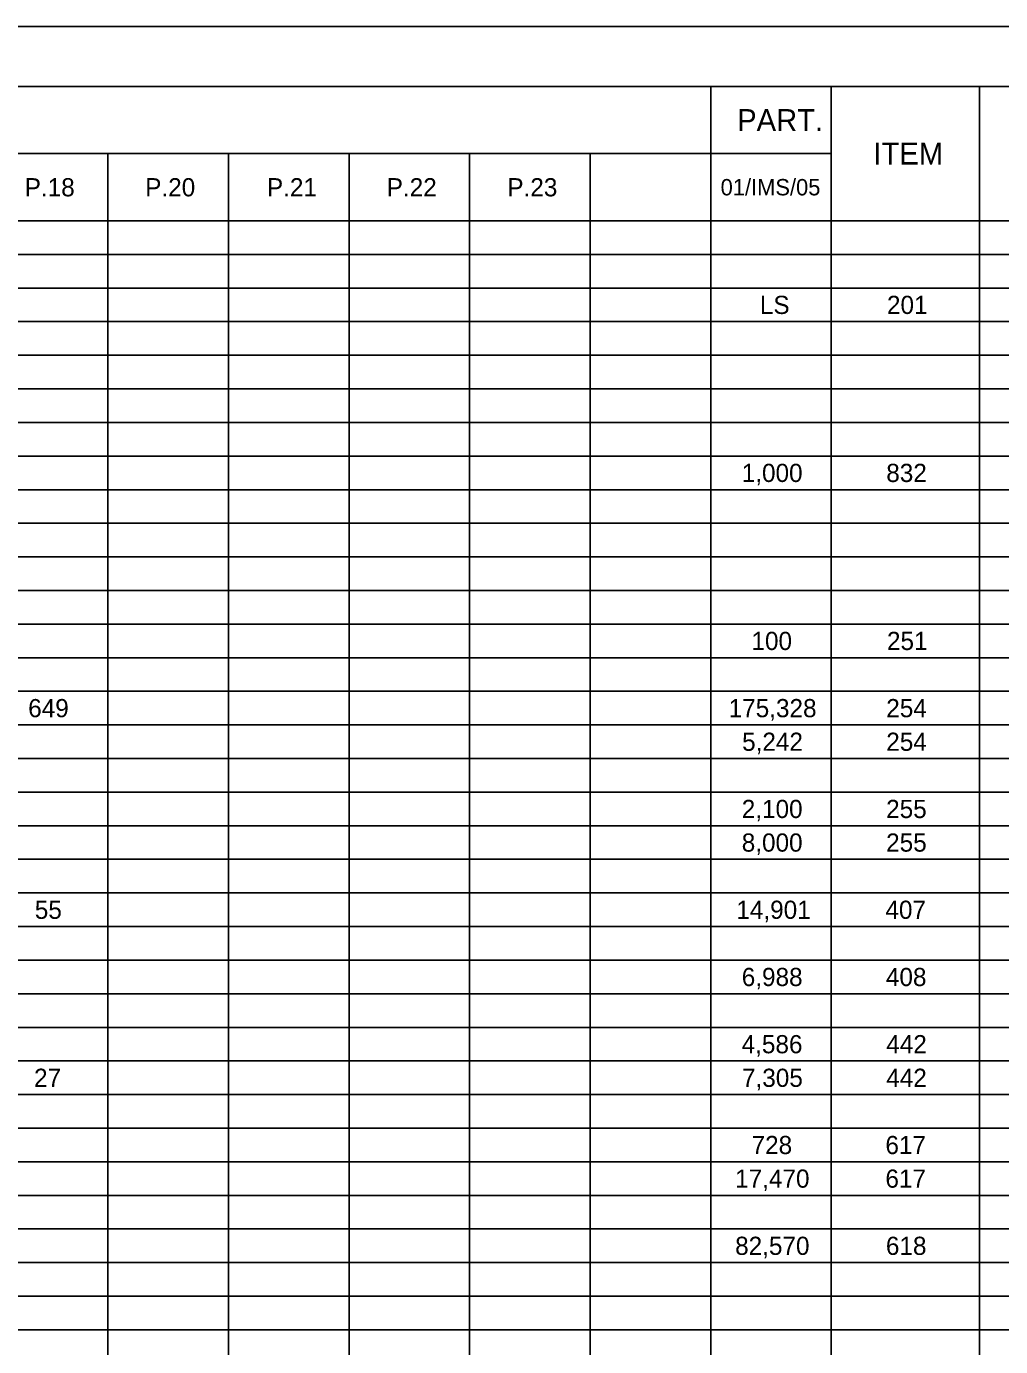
# Model space of a CAD drawing. Extents: x 0 to 806, y -250 to 22.
# Drawn here: x 8.86 to 16.97, y 11 to 22 of the extents above; entities that cross this region are included whole.
import ezdxf

# ---------------------------------------------------------------- set-up
doc = ezdxf.new("R2010")
doc.units = 0
for name, color, linetype in [('SH_Border', 7, 'Continuous'), ('SH_Cut_Line', 7, 'Continuous'), ('SH_Text', 7, 'Continuous')]:
    doc.layers.add(name, color=color, linetype=linetype)

msp = doc.modelspace()

# ---------------------------------------------------------------- linework, layer by layer
at = {"layer": 'SH_Border'}
msp.add_lwpolyline([(1.5, 21.5), (33.5, 21.5), (33.5, 0.5), (1.5, 0.5)], close=True, dxfattribs=at)
at = {"layer": 'SH_Cut_Line'}
msp.add_lwpolyline([(0, 0), (34, 0), (34, 22), (0, 22)], close=True, dxfattribs=at)
at = {"layer": 'SH_Text'}
for p, q in [((1.5, 21.5), (32, 21.5)), ((14.56, 21.5), (14.56, 0.5)), ((15.564, 21.5), (15.564, 0.5)), ((16.799, 21.5), (16.799, 0.5)), ((1.5, 20.94), (15.564, 20.94)), ((9.537, 20.94), (9.537, 0.5)), ((10.541, 20.94), (10.541, 0.5)), ((11.546, 20.94), (11.546, 0.5)), ((12.55, 20.94), (12.55, 0.5)), ((13.555, 20.94), (13.555, 0.5)), ((1.5, 20.38), (32, 20.38)), ((1.5, 20.1), (32, 20.1)), ((1.5, 19.82), (32, 19.82)), ((1.5, 19.54), (32, 19.54)), ((1.5, 19.26), (32, 19.26)), ((1.5, 18.98), (32, 18.98)), ((1.5, 18.7), (32, 18.7)), ((1.5, 18.42), (32, 18.42)), ((1.5, 18.14), (32, 18.14)), ((1.5, 17.86), (32, 17.86)), ((1.5, 17.58), (32, 17.58)), ((1.5, 17.3), (32, 17.3)), ((1.5, 17.02), (32, 17.02)), ((1.5, 16.74), (32, 16.74)), ((1.5, 16.46), (32, 16.46)), ((1.5, 16.18), (32, 16.18)), ((1.5, 15.9), (32, 15.9)), ((1.5, 15.62), (32, 15.62)), ((1.5, 15.34), (32, 15.34)), ((1.5, 15.06), (32, 15.06)), ((1.5, 14.78), (32, 14.78)), ((1.5, 14.5), (32, 14.5)), ((1.5, 14.22), (32, 14.22)), ((1.5, 13.94), (32, 13.94)), ((1.5, 13.66), (32, 13.66)), ((1.5, 13.38), (32, 13.38)), ((1.5, 13.1), (32, 13.1)), ((1.5, 12.82), (32, 12.82)), ((1.5, 12.54), (32, 12.54)), ((1.5, 12.26), (32, 12.26)), ((1.5, 11.98), (32, 11.98)), ((1.5, 11.7), (32, 11.7)), ((1.5, 11.42), (32, 11.42)), ((1.5, 11.14), (32, 11.14))]:
    msp.add_line(p, q, dxfattribs=at)

# ---------------------------------------------------------------- texts
for s, height, p in [('PART.', 0.1818, (14.78, 21.129)), ('ITEM', 0.1818, (15.915, 20.849)), ('P.18', 0.1515, (8.844, 20.584)), ('P.20', 0.1515, (9.848, 20.584)), ('P.21', 0.1515, (10.862, 20.584)), ('P.22', 0.1515, (11.86, 20.584)), ('P.23', 0.1515, (12.865, 20.584)), ('01/IMS/05', 0.1364, (14.642, 20.592)), ('LS', 0.1515, (14.969, 19.604)), ('201', 0.1515, (16.028, 19.604)), ('1,000', 0.1515, (14.818, 18.204)), ('832', 0.1515, (16.022, 18.204)), ('100', 0.1515, (14.899, 16.804)), ('251', 0.1515, (16.028, 16.804)), ('649', 0.1515, (8.873, 16.244)), ('175,328', 0.1515, (14.709, 16.244)), ('254', 0.1515, (16.022, 16.244)), ('5,242', 0.1515, (14.821, 15.964)), ('254', 0.1515, (16.022, 15.964)), ('2,100', 0.1515, (14.818, 15.404)), ('255', 0.1515, (16.021, 15.404)), ('8,000', 0.1515, (14.818, 15.124)), ('255', 0.1515, (16.021, 15.124)), ('55', 0.1515, (8.928, 14.564)), ('14,901', 0.1515, (14.773, 14.564)), ('407', 0.1515, (16.015, 14.564)), ('6,988', 0.1515, (14.818, 14.004)), ('408', 0.1515, (16.019, 14.004)), ('4,586', 0.1515, (14.817, 13.444)), ('442', 0.1515, (16.022, 13.444)), ('27', 0.1515, (8.922, 13.164)), ('7,305', 0.1515, (14.82, 13.164)), ('442', 0.1515, (16.022, 13.164)), ('728', 0.1515, (14.9, 12.604)), ('617', 0.1515, (16.015, 12.604)), ('17,470', 0.1515, (14.763, 12.324)), ('617', 0.1515, (16.015, 12.324)), ('82,570', 0.1515, (14.763, 11.764)), ('618', 0.1515, (16.019, 11.764))]:
    msp.add_text(s, height=height, dxfattribs=at).set_placement(p)

doc.saveas('drawing.dxf')
